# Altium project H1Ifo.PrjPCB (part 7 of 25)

## Sheet IfoIsc2B.SchDoc: D1800185
size C; Engineer: Daniel Sigg; DocumentNumber: 6; Revision: 4; SheetNumber: 6; SheetTotal: 11
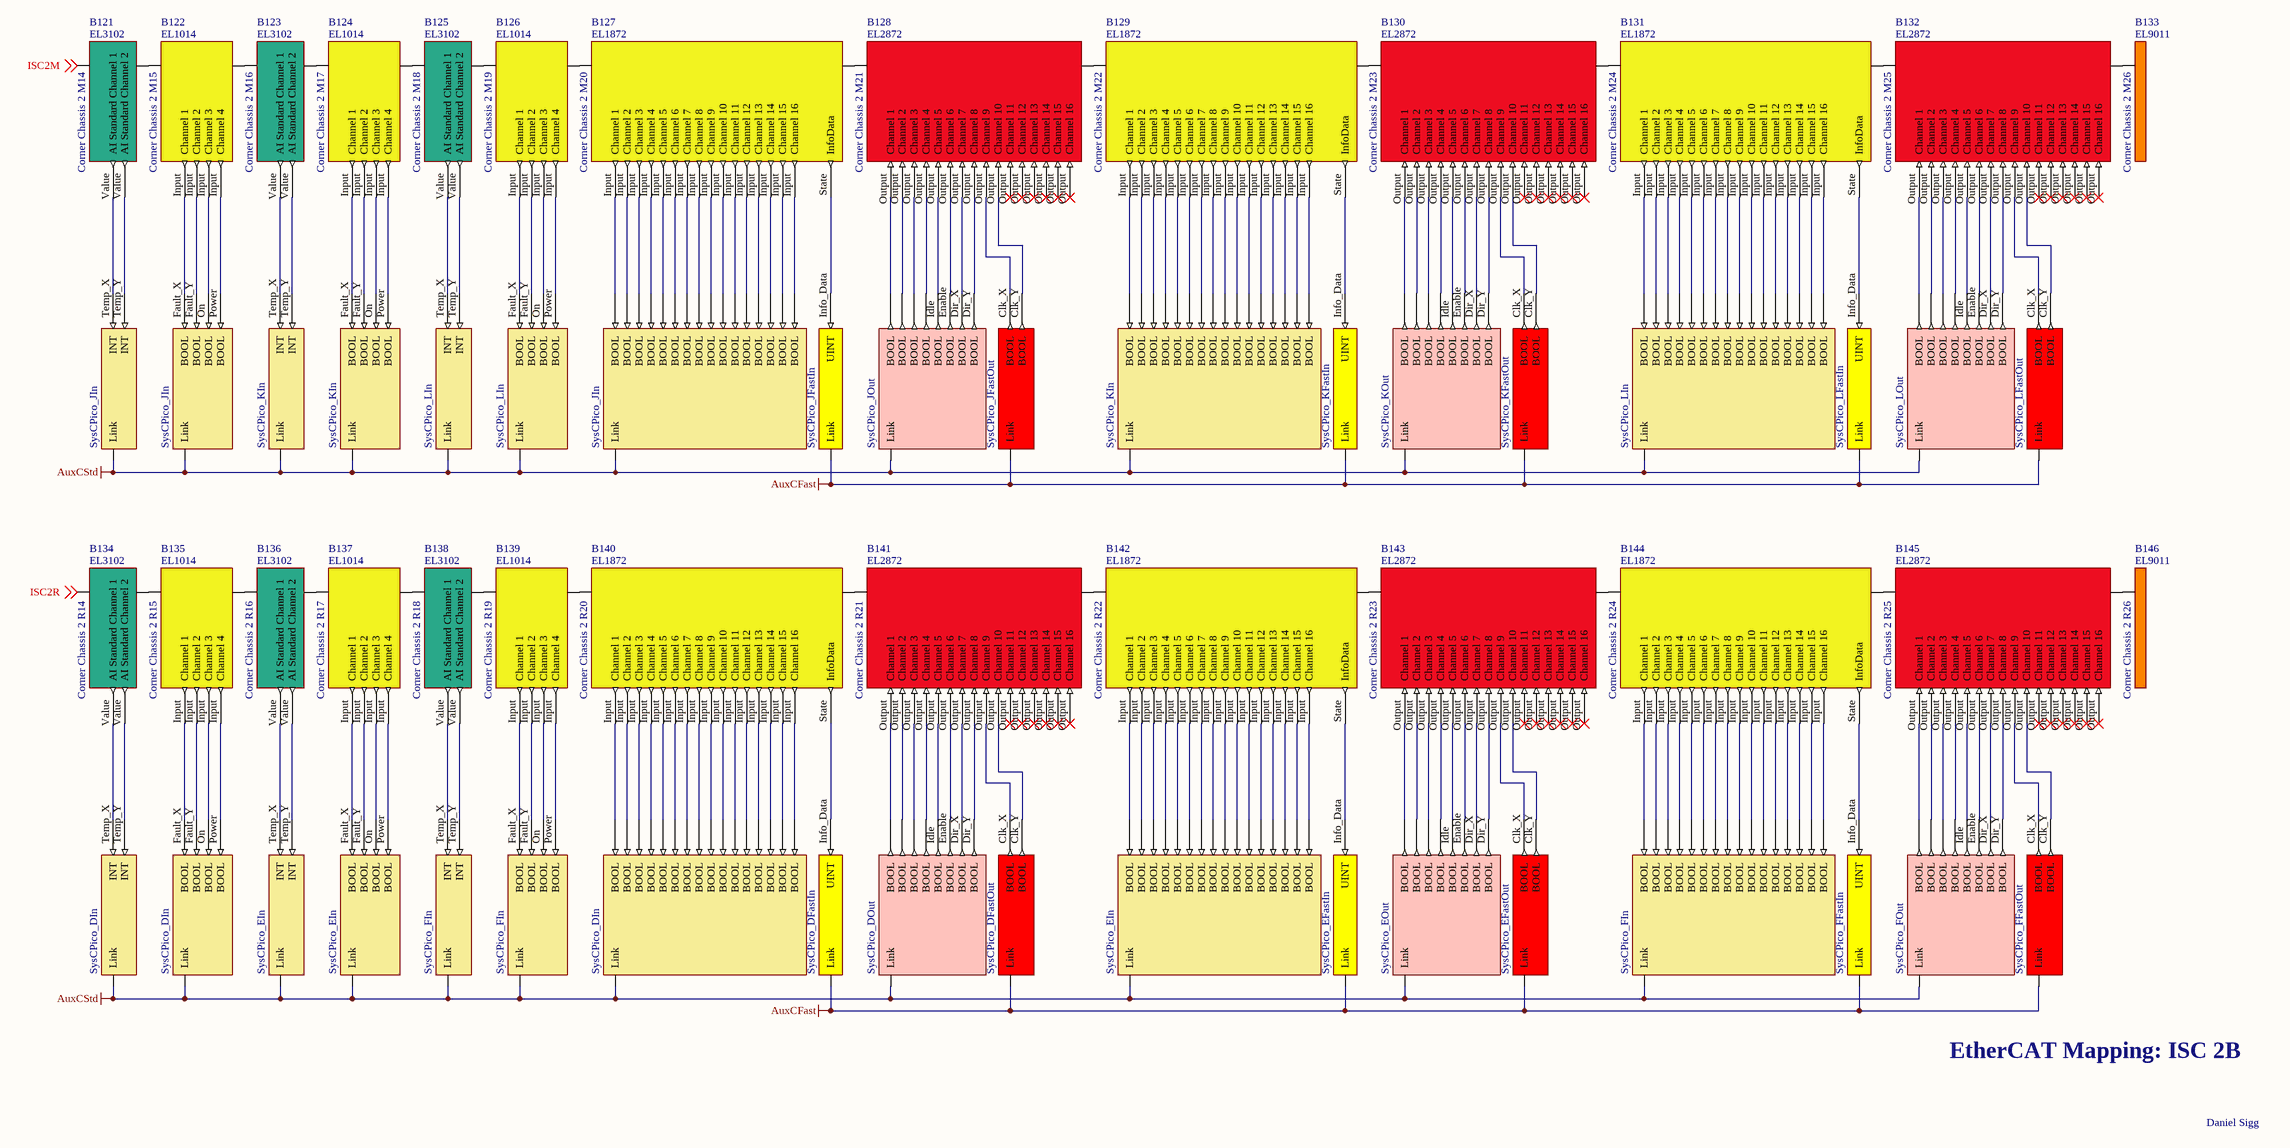
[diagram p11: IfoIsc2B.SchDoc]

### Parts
B121  Corner Chassis 2 M14  Part Number: EL3102  (mechanical)
B122  Corner Chassis 2 M15  Part Number: EL1014  (mechanical)
B123  Corner Chassis 2 M16  Part Number: EL3102  (mechanical)
B124  Corner Chassis 2 M17  Part Number: EL1014  (mechanical)
B125  Corner Chassis 2 M18  Part Number: EL3102  (mechanical)
B126  Corner Chassis 2 M19  Part Number: EL1014  (mechanical)
B127  Corner Chassis 2 M20  Part Number: EL1872  (mechanical)
B128  Corner Chassis 2 M21  Part Number: EL2872  (mechanical)
B129  Corner Chassis 2 M22  Part Number: EL1872  (mechanical)
B130  Corner Chassis 2 M23  Part Number: EL2872  (mechanical)
B131  Corner Chassis 2 M24  Part Number: EL1872  (mechanical)
B132  Corner Chassis 2 M25  Part Number: EL2872  (mechanical)
B133  Corner Chassis 2 M26  Part Number: EL9011  (mechanical)
B134  Corner Chassis 2 R14  Part Number: EL3102  (mechanical)
B135  Corner Chassis 2 R15  Part Number: EL1014  (mechanical)
B136  Corner Chassis 2 R16  Part Number: EL3102  (mechanical)
B137  Corner Chassis 2 R17  Part Number: EL1014  (mechanical)
B138  Corner Chassis 2 R18  Part Number: EL3102  (mechanical)
B139  Corner Chassis 2 R19  Part Number: EL1014  (mechanical)
B140  Corner Chassis 2 R20  Part Number: EL1872  (mechanical)
B141  Corner Chassis 2 R21  Part Number: EL2872  (mechanical)
B142  Corner Chassis 2 R22  Part Number: EL1872  (mechanical)
B143  Corner Chassis 2 R23  Part Number: EL2872  (mechanical)
B144  Corner Chassis 2 R24  Part Number: EL1872  (mechanical)
B145  Corner Chassis 2 R25  Part Number: EL2872  (mechanical)
B146  Corner Chassis 2 R26  Part Number: EL9011  (mechanical)
V74  SysCPico_DIn  (parts A,B,C of 3)  (no BOM)
V75  SysCPico_EIn  (parts A,B,C of 3)  (no BOM)
V76  SysCPico_FIn  (parts A,B,C of 3)  (no BOM)
V192  SysCPico_JFastIn  (no BOM)
V193  SysCPico_JOut  (no BOM)
V194  SysCPico_JFastOut  (no BOM)
V195  SysCPico_KFastIn  (no BOM)
V196  SysCPico_KOut  (no BOM)
V197  SysCPico_KFastOut  (no BOM)
V198  SysCPico_LFastIn  (no BOM)
V199  SysCPico_LOut  (no BOM)
V200  SysCPico_LFastOut  (no BOM)
V201  SysCPico_DFastIn  (no BOM)
V202  SysCPico_DOut  (no BOM)
V203  SysCPico_DFastOut  (no BOM)
V204  SysCPico_EFastIn  (no BOM)
V205  SysCPico_EOut  (no BOM)
V206  SysCPico_EFastOut  (no BOM)
V207  SysCPico_FFastIn  (no BOM)
V208  SysCPico_FOut  (no BOM)
V209  SysCPico_FFastOut  (no BOM)
V696  SysCPico_JIn  (parts A,B,C of 3)  (no BOM)
V697  SysCPico_KIn  (parts A,B,C of 3)  (no BOM)
V698  SysCPico_LIn  (parts A,B,C of 3)  (no BOM)

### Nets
AuxCFast: V192.0(Link) V194.0(Link) V195.0(Link) V197.0(Link) V198.0(Link) V200.0(Link) V201.0(Link) V203.0(Link) V204.0(Link) V206.0(Link) V207.0(Link) V209.0(Link)
AuxCStd: V74.0(Link) V74.1(Link) V74.2(Link) V75.0(Link) V75.1(Link) V75.2(Link) V76.0(Link) V76.1(Link) V76.2(Link) V193.0(Link) V196.0(Link) V199.0(Link) V202.0(Link) V205.0(Link) V208.0(Link) V696.0(Link) V696.1(Link) V696.2(Link) V697.0(Link) V697.1(Link) V697.2(Link) V698.0(Link) V698.1(Link) V698.2(Link)
ISC2M: B121.Ebus(A) ; off-sheet ISC2M
ISC2R: B134.Ebus(A) ; off-sheet ISC2R
NetB121_Ebus: B121.Ebus(B) B122.Ebus(A)
NetB121_Value: B121.Value(AI_Standard_Channel_1) V696.Temp_X(INT)
NetB121_Value: B121.Value(AI_Standard_Channel_2) V696.Temp_Y(INT)  [a separate net that carries the same name]
NetB122_Ebus: B122.Ebus(B) B123.Ebus(A)
NetB122_Input: B122.Input(Channel_1) V696.Fault_X(BOOL)
NetB122_Input: B122.Input(Channel_2) V696.Fault_Y(BOOL)  [a separate net that carries the same name]
NetB122_Input: B122.Input(Channel_3) V696.On(BOOL)  [a separate net that carries the same name]
NetB122_Input: B122.Input(Channel_4) V696.Power(BOOL)  [a separate net that carries the same name]
NetB123_Ebus: B123.Ebus(B) B124.Ebus(A)
NetB123_Value: B123.Value(AI_Standard_Channel_1) V697.Temp_X(INT)
NetB123_Value: B123.Value(AI_Standard_Channel_2) V697.Temp_Y(INT)  [a separate net that carries the same name]
NetB124_Ebus: B124.Ebus(B) B125.Ebus(A)
NetB124_Input: B124.Input(Channel_1) V697.Fault_X(BOOL)
NetB124_Input: B124.Input(Channel_2) V697.Fault_Y(BOOL)  [a separate net that carries the same name]
NetB124_Input: B124.Input(Channel_3) V697.On(BOOL)  [a separate net that carries the same name]
NetB124_Input: B124.Input(Channel_4) V697.Power(BOOL)  [a separate net that carries the same name]
NetB125_Ebus: B125.Ebus(B) B126.Ebus(A)
NetB125_Value: B125.Value(AI_Standard_Channel_1) V698.Temp_X(INT)
NetB125_Value: B125.Value(AI_Standard_Channel_2) V698.Temp_Y(INT)  [a separate net that carries the same name]
NetB126_Ebus: B126.Ebus(B) B127.Ebus(A)
NetB126_Input: B126.Input(Channel_1) V698.Fault_X(BOOL)
NetB126_Input: B126.Input(Channel_2) V698.Fault_Y(BOOL)  [a separate net that carries the same name]
NetB126_Input: B126.Input(Channel_3) V698.On(BOOL)  [a separate net that carries the same name]
NetB126_Input: B126.Input(Channel_4) V698.Power(BOOL)  [a separate net that carries the same name]
NetB127_Ebus: B127.Ebus(B) B128.Ebus(A)
NetB127_Input: B127.Input(Channel_1) V696.MotorX1(BOOL)
NetB127_Input: B127.Input(Channel_2) V696.MotorX2(BOOL)  [a separate net that carries the same name]
NetB127_Input: B127.Input(Channel_3) V696.MotorX3(BOOL)  [a separate net that carries the same name]
NetB127_Input: B127.Input(Channel_4) V696.MotorX4(BOOL)  [a separate net that carries the same name]
NetB127_Input: B127.Input(Channel_5) V696.MotorX5(BOOL)  [a separate net that carries the same name]
NetB127_Input: B127.Input(Channel_6) V696.MotorX6(BOOL)  [a separate net that carries the same name]
NetB127_Input: B127.Input(Channel_7) V696.MotorX7(BOOL)  [a separate net that carries the same name]
NetB127_Input: B127.Input(Channel_8) V696.MotorX8(BOOL)  [a separate net that carries the same name]
NetB127_Input: B127.Input(Channel_9) V696.MotorY1(BOOL)  [a separate net that carries the same name]
NetB127_Input: B127.Input(Channel_10) V696.MotorY2(BOOL)  [a separate net that carries the same name]
NetB127_Input: B127.Input(Channel_11) V696.MotorY3(BOOL)  [a separate net that carries the same name]
NetB127_Input: B127.Input(Channel_12) V696.MotorY4(BOOL)  [a separate net that carries the same name]
NetB127_Input: B127.Input(Channel_13) V696.MotorY5(BOOL)  [a separate net that carries the same name]
NetB127_Input: B127.Input(Channel_14) V696.MotorY6(BOOL)  [a separate net that carries the same name]
NetB127_Input: B127.Input(Channel_15) V696.MotorY7(BOOL)  [a separate net that carries the same name]
NetB127_Input: B127.Input(Channel_16) V696.MotorY8(BOOL)  [a separate net that carries the same name]
NetB127_State: B127.State(InfoData) V192.Info_Data(UINT)
NetB128_Ebus: B128.Ebus(B) B129.Ebus(A)
NetB128_Output: B128.Output(Channel_1) V193.MOTOR3(BOOL)
NetB128_Output: B128.Output(Channel_2) V193.MOTOR2(BOOL)  [a separate net that carries the same name]
NetB128_Output: B128.Output(Channel_3) V193.MOTOR1(BOOL)  [a separate net that carries the same name]
NetB128_Output: B128.Output(Channel_4) V193.MOTOR4(BOOL)  [a separate net that carries the same name]
NetB128_Output: B128.Output(Channel_5) V193.Idle(BOOL)  [a separate net that carries the same name]
NetB128_Output: B128.Output(Channel_6) V193.Enable(BOOL)  [a separate net that carries the same name]
NetB128_Output: B128.Output(Channel_7) V193.Dir_X(BOOL)  [a separate net that carries the same name]
NetB128_Output: B128.Output(Channel_8) V193.Dir_Y(BOOL)  [a separate net that carries the same name]
NetB128_Output: B128.Output(Channel_9) V194.Clk_X(BOOL)  [a separate net that carries the same name]
NetB128_Output: B128.Output(Channel_10) V194.Clk_Y(BOOL)  [a separate net that carries the same name]
NetB129_Ebus: B129.Ebus(B) B130.Ebus(A)
NetB129_Input: B129.Input(Channel_1) V697.MotorX1(BOOL)
NetB129_Input: B129.Input(Channel_2) V697.MotorX2(BOOL)  [a separate net that carries the same name]
NetB129_Input: B129.Input(Channel_3) V697.MotorX3(BOOL)  [a separate net that carries the same name]
NetB129_Input: B129.Input(Channel_4) V697.MotorX4(BOOL)  [a separate net that carries the same name]
NetB129_Input: B129.Input(Channel_5) V697.MotorX5(BOOL)  [a separate net that carries the same name]
NetB129_Input: B129.Input(Channel_6) V697.MotorX6(BOOL)  [a separate net that carries the same name]
NetB129_Input: B129.Input(Channel_7) V697.MotorX7(BOOL)  [a separate net that carries the same name]
NetB129_Input: B129.Input(Channel_8) V697.MotorX8(BOOL)  [a separate net that carries the same name]
NetB129_Input: B129.Input(Channel_9) V697.MotorY1(BOOL)  [a separate net that carries the same name]
NetB129_Input: B129.Input(Channel_10) V697.MotorY2(BOOL)  [a separate net that carries the same name]
NetB129_Input: B129.Input(Channel_11) V697.MotorY3(BOOL)  [a separate net that carries the same name]
NetB129_Input: B129.Input(Channel_12) V697.MotorY4(BOOL)  [a separate net that carries the same name]
NetB129_Input: B129.Input(Channel_13) V697.MotorY5(BOOL)  [a separate net that carries the same name]
NetB129_Input: B129.Input(Channel_14) V697.MotorY6(BOOL)  [a separate net that carries the same name]
NetB129_Input: B129.Input(Channel_15) V697.MotorY7(BOOL)  [a separate net that carries the same name]
NetB129_Input: B129.Input(Channel_16) V697.MotorY8(BOOL)  [a separate net that carries the same name]
NetB129_State: B129.State(InfoData) V195.Info_Data(UINT)
NetB130_Ebus: B130.Ebus(B) B131.Ebus(A)
NetB130_Output: B130.Output(Channel_1) V196.MOTOR3(BOOL)
NetB130_Output: B130.Output(Channel_2) V196.MOTOR2(BOOL)  [a separate net that carries the same name]
NetB130_Output: B130.Output(Channel_3) V196.MOTOR1(BOOL)  [a separate net that carries the same name]
NetB130_Output: B130.Output(Channel_4) V196.MOTOR4(BOOL)  [a separate net that carries the same name]
NetB130_Output: B130.Output(Channel_5) V196.Idle(BOOL)  [a separate net that carries the same name]
NetB130_Output: B130.Output(Channel_6) V196.Enable(BOOL)  [a separate net that carries the same name]
NetB130_Output: B130.Output(Channel_7) V196.Dir_X(BOOL)  [a separate net that carries the same name]
NetB130_Output: B130.Output(Channel_8) V196.Dir_Y(BOOL)  [a separate net that carries the same name]
NetB130_Output: B130.Output(Channel_9) V197.Clk_X(BOOL)  [a separate net that carries the same name]
NetB130_Output: B130.Output(Channel_10) V197.Clk_Y(BOOL)  [a separate net that carries the same name]
NetB131_Ebus: B131.Ebus(B) B132.Ebus(A)
NetB131_Input: B131.Input(Channel_1) V698.MotorX1(BOOL)
NetB131_Input: B131.Input(Channel_2) V698.MotorX2(BOOL)  [a separate net that carries the same name]
NetB131_Input: B131.Input(Channel_3) V698.MotorX3(BOOL)  [a separate net that carries the same name]
NetB131_Input: B131.Input(Channel_4) V698.MotorX4(BOOL)  [a separate net that carries the same name]
NetB131_Input: B131.Input(Channel_5) V698.MotorX5(BOOL)  [a separate net that carries the same name]
NetB131_Input: B131.Input(Channel_6) V698.MotorX6(BOOL)  [a separate net that carries the same name]
NetB131_Input: B131.Input(Channel_7) V698.MotorX7(BOOL)  [a separate net that carries the same name]
NetB131_Input: B131.Input(Channel_8) V698.MotorX8(BOOL)  [a separate net that carries the same name]
NetB131_Input: B131.Input(Channel_9) V698.MotorY1(BOOL)  [a separate net that carries the same name]
NetB131_Input: B131.Input(Channel_10) V698.MotorY2(BOOL)  [a separate net that carries the same name]
NetB131_Input: B131.Input(Channel_11) V698.MotorY3(BOOL)  [a separate net that carries the same name]
NetB131_Input: B131.Input(Channel_12) V698.MotorY4(BOOL)  [a separate net that carries the same name]
NetB131_Input: B131.Input(Channel_13) V698.MotorY5(BOOL)  [a separate net that carries the same name]
NetB131_Input: B131.Input(Channel_14) V698.MotorY6(BOOL)  [a separate net that carries the same name]
NetB131_Input: B131.Input(Channel_15) V698.MotorY7(BOOL)  [a separate net that carries the same name]
NetB131_Input: B131.Input(Channel_16) V698.MotorY8(BOOL)  [a separate net that carries the same name]
NetB131_State: B131.State(InfoData) V198.Info_Data(UINT)
NetB132_Ebus: B132.Ebus(B) B133.Ebus(A)
NetB132_Output: B132.Output(Channel_1) V199.MOTOR3(BOOL)
NetB132_Output: B132.Output(Channel_2) V199.MOTOR2(BOOL)  [a separate net that carries the same name]
NetB132_Output: B132.Output(Channel_3) V199.MOTOR1(BOOL)  [a separate net that carries the same name]
NetB132_Output: B132.Output(Channel_4) V199.MOTOR4(BOOL)  [a separate net that carries the same name]
NetB132_Output: B132.Output(Channel_5) V199.Idle(BOOL)  [a separate net that carries the same name]
NetB132_Output: B132.Output(Channel_6) V199.Enable(BOOL)  [a separate net that carries the same name]
NetB132_Output: B132.Output(Channel_7) V199.Dir_X(BOOL)  [a separate net that carries the same name]
NetB132_Output: B132.Output(Channel_8) V199.Dir_Y(BOOL)  [a separate net that carries the same name]
NetB132_Output: B132.Output(Channel_9) V200.Clk_X(BOOL)  [a separate net that carries the same name]
NetB132_Output: B132.Output(Channel_10) V200.Clk_Y(BOOL)  [a separate net that carries the same name]
NetB134_Ebus: B134.Ebus(B) B135.Ebus(A)
NetB134_Value: B134.Value(AI_Standard_Channel_1) V74.Temp_X(INT)
NetB134_Value: B134.Value(AI_Standard_Channel_2) V74.Temp_Y(INT)  [a separate net that carries the same name]
NetB135_Ebus: B135.Ebus(B) B136.Ebus(A)
NetB135_Input: B135.Input(Channel_1) V74.Fault_X(BOOL)
NetB135_Input: B135.Input(Channel_2) V74.Fault_Y(BOOL)  [a separate net that carries the same name]
NetB135_Input: B135.Input(Channel_3) V74.On(BOOL)  [a separate net that carries the same name]
NetB135_Input: B135.Input(Channel_4) V74.Power(BOOL)  [a separate net that carries the same name]
NetB136_Ebus: B136.Ebus(B) B137.Ebus(A)
NetB136_Value: B136.Value(AI_Standard_Channel_1) V75.Temp_X(INT)
NetB136_Value: B136.Value(AI_Standard_Channel_2) V75.Temp_Y(INT)  [a separate net that carries the same name]
NetB137_Ebus: B137.Ebus(B) B138.Ebus(A)
NetB137_Input: B137.Input(Channel_1) V75.Fault_X(BOOL)
NetB137_Input: B137.Input(Channel_2) V75.Fault_Y(BOOL)  [a separate net that carries the same name]
NetB137_Input: B137.Input(Channel_3) V75.On(BOOL)  [a separate net that carries the same name]
NetB137_Input: B137.Input(Channel_4) V75.Power(BOOL)  [a separate net that carries the same name]
NetB138_Ebus: B138.Ebus(B) B139.Ebus(A)
NetB138_Value: B138.Value(AI_Standard_Channel_1) V76.Temp_X(INT)
NetB138_Value: B138.Value(AI_Standard_Channel_2) V76.Temp_Y(INT)  [a separate net that carries the same name]
NetB139_Ebus: B139.Ebus(B) B140.Ebus(A)
NetB139_Input: B139.Input(Channel_1) V76.Fault_X(BOOL)
NetB139_Input: B139.Input(Channel_2) V76.Fault_Y(BOOL)  [a separate net that carries the same name]
NetB139_Input: B139.Input(Channel_3) V76.On(BOOL)  [a separate net that carries the same name]
NetB139_Input: B139.Input(Channel_4) V76.Power(BOOL)  [a separate net that carries the same name]
NetB140_Ebus: B140.Ebus(B) B141.Ebus(A)
NetB140_Input: B140.Input(Channel_1) V74.MotorX1(BOOL)
NetB140_Input: B140.Input(Channel_2) V74.MotorX2(BOOL)  [a separate net that carries the same name]
NetB140_Input: B140.Input(Channel_3) V74.MotorX3(BOOL)  [a separate net that carries the same name]
NetB140_Input: B140.Input(Channel_4) V74.MotorX4(BOOL)  [a separate net that carries the same name]
NetB140_Input: B140.Input(Channel_5) V74.MotorX5(BOOL)  [a separate net that carries the same name]
NetB140_Input: B140.Input(Channel_6) V74.MotorX6(BOOL)  [a separate net that carries the same name]
NetB140_Input: B140.Input(Channel_7) V74.MotorX7(BOOL)  [a separate net that carries the same name]
NetB140_Input: B140.Input(Channel_8) V74.MotorX8(BOOL)  [a separate net that carries the same name]
NetB140_Input: B140.Input(Channel_9) V74.MotorY1(BOOL)  [a separate net that carries the same name]
NetB140_Input: B140.Input(Channel_10) V74.MotorY2(BOOL)  [a separate net that carries the same name]
NetB140_Input: B140.Input(Channel_11) V74.MotorY3(BOOL)  [a separate net that carries the same name]
NetB140_Input: B140.Input(Channel_12) V74.MotorY4(BOOL)  [a separate net that carries the same name]
NetB140_Input: B140.Input(Channel_13) V74.MotorY5(BOOL)  [a separate net that carries the same name]
NetB140_Input: B140.Input(Channel_14) V74.MotorY6(BOOL)  [a separate net that carries the same name]
NetB140_Input: B140.Input(Channel_15) V74.MotorY7(BOOL)  [a separate net that carries the same name]
NetB140_Input: B140.Input(Channel_16) V74.MotorY8(BOOL)  [a separate net that carries the same name]
NetB140_State: B140.State(InfoData) V201.Info_Data(UINT)
NetB141_Ebus: B141.Ebus(B) B142.Ebus(A)
NetB141_Output: B141.Output(Channel_1) V202.MOTOR3(BOOL)
NetB141_Output: B141.Output(Channel_2) V202.MOTOR2(BOOL)  [a separate net that carries the same name]
NetB141_Output: B141.Output(Channel_3) V202.MOTOR1(BOOL)  [a separate net that carries the same name]
NetB141_Output: B141.Output(Channel_4) V202.MOTOR4(BOOL)  [a separate net that carries the same name]
NetB141_Output: B141.Output(Channel_5) V202.Idle(BOOL)  [a separate net that carries the same name]
NetB141_Output: B141.Output(Channel_6) V202.Enable(BOOL)  [a separate net that carries the same name]
NetB141_Output: B141.Output(Channel_7) V202.Dir_X(BOOL)  [a separate net that carries the same name]
NetB141_Output: B141.Output(Channel_8) V202.Dir_Y(BOOL)  [a separate net that carries the same name]
NetB141_Output: B141.Output(Channel_9) V203.Clk_X(BOOL)  [a separate net that carries the same name]
NetB141_Output: B141.Output(Channel_10) V203.Clk_Y(BOOL)  [a separate net that carries the same name]
NetB142_Ebus: B142.Ebus(B) B143.Ebus(A)
NetB142_Input: B142.Input(Channel_1) V75.MotorX1(BOOL)
NetB142_Input: B142.Input(Channel_2) V75.MotorX2(BOOL)  [a separate net that carries the same name]
NetB142_Input: B142.Input(Channel_3) V75.MotorX3(BOOL)  [a separate net that carries the same name]
NetB142_Input: B142.Input(Channel_4) V75.MotorX4(BOOL)  [a separate net that carries the same name]
NetB142_Input: B142.Input(Channel_5) V75.MotorX5(BOOL)  [a separate net that carries the same name]
NetB142_Input: B142.Input(Channel_6) V75.MotorX6(BOOL)  [a separate net that carries the same name]
NetB142_Input: B142.Input(Channel_7) V75.MotorX7(BOOL)  [a separate net that carries the same name]
NetB142_Input: B142.Input(Channel_8) V75.MotorX8(BOOL)  [a separate net that carries the same name]
NetB142_Input: B142.Input(Channel_9) V75.MotorY1(BOOL)  [a separate net that carries the same name]
NetB142_Input: B142.Input(Channel_10) V75.MotorY2(BOOL)  [a separate net that carries the same name]
NetB142_Input: B142.Input(Channel_11) V75.MotorY3(BOOL)  [a separate net that carries the same name]
NetB142_Input: B142.Input(Channel_12) V75.MotorY4(BOOL)  [a separate net that carries the same name]
NetB142_Input: B142.Input(Channel_13) V75.MotorY5(BOOL)  [a separate net that carries the same name]
NetB142_Input: B142.Input(Channel_14) V75.MotorY6(BOOL)  [a separate net that carries the same name]
NetB142_Input: B142.Input(Channel_15) V75.MotorY7(BOOL)  [a separate net that carries the same name]
NetB142_Input: B142.Input(Channel_16) V75.MotorY8(BOOL)  [a separate net that carries the same name]
NetB142_State: B142.State(InfoData) V204.Info_Data(UINT)
NetB143_Ebus: B143.Ebus(B) B144.Ebus(A)
NetB143_Output: B143.Output(Channel_1) V205.MOTOR3(BOOL)
NetB143_Output: B143.Output(Channel_2) V205.MOTOR2(BOOL)  [a separate net that carries the same name]
NetB143_Output: B143.Output(Channel_3) V205.MOTOR1(BOOL)  [a separate net that carries the same name]
NetB143_Output: B143.Output(Channel_4) V205.MOTOR4(BOOL)  [a separate net that carries the same name]
NetB143_Output: B143.Output(Channel_5) V205.Idle(BOOL)  [a separate net that carries the same name]
NetB143_Output: B143.Output(Channel_6) V205.Enable(BOOL)  [a separate net that carries the same name]
NetB143_Output: B143.Output(Channel_7) V205.Dir_X(BOOL)  [a separate net that carries the same name]
NetB143_Output: B143.Output(Channel_8) V205.Dir_Y(BOOL)  [a separate net that carries the same name]
NetB143_Output: B143.Output(Channel_9) V206.Clk_X(BOOL)  [a separate net that carries the same name]
NetB143_Output: B143.Output(Channel_10) V206.Clk_Y(BOOL)  [a separate net that carries the same name]
NetB144_Ebus: B144.Ebus(B) B145.Ebus(A)
NetB144_Input: B144.Input(Channel_1) V76.MotorX1(BOOL)
NetB144_Input: B144.Input(Channel_2) V76.MotorX2(BOOL)  [a separate net that carries the same name]
NetB144_Input: B144.Input(Channel_3) V76.MotorX3(BOOL)  [a separate net that carries the same name]
NetB144_Input: B144.Input(Channel_4) V76.MotorX4(BOOL)  [a separate net that carries the same name]
NetB144_Input: B144.Input(Channel_5) V76.MotorX5(BOOL)  [a separate net that carries the same name]
NetB144_Input: B144.Input(Channel_6) V76.MotorX6(BOOL)  [a separate net that carries the same name]
NetB144_Input: B144.Input(Channel_7) V76.MotorX7(BOOL)  [a separate net that carries the same name]
NetB144_Input: B144.Input(Channel_8) V76.MotorX8(BOOL)  [a separate net that carries the same name]
NetB144_Input: B144.Input(Channel_9) V76.MotorY1(BOOL)  [a separate net that carries the same name]
NetB144_Input: B144.Input(Channel_10) V76.MotorY2(BOOL)  [a separate net that carries the same name]
NetB144_Input: B144.Input(Channel_11) V76.MotorY3(BOOL)  [a separate net that carries the same name]
NetB144_Input: B144.Input(Channel_12) V76.MotorY4(BOOL)  [a separate net that carries the same name]
NetB144_Input: B144.Input(Channel_13) V76.MotorY5(BOOL)  [a separate net that carries the same name]
NetB144_Input: B144.Input(Channel_14) V76.MotorY6(BOOL)  [a separate net that carries the same name]
NetB144_Input: B144.Input(Channel_15) V76.MotorY7(BOOL)  [a separate net that carries the same name]
NetB144_Input: B144.Input(Channel_16) V76.MotorY8(BOOL)  [a separate net that carries the same name]
NetB144_State: B144.State(InfoData) V207.Info_Data(UINT)
NetB145_Ebus: B145.Ebus(B) B146.Ebus(A)
NetB145_Output: B145.Output(Channel_1) V208.MOTOR3(BOOL)
NetB145_Output: B145.Output(Channel_2) V208.MOTOR2(BOOL)  [a separate net that carries the same name]
NetB145_Output: B145.Output(Channel_3) V208.MOTOR1(BOOL)  [a separate net that carries the same name]
NetB145_Output: B145.Output(Channel_4) V208.MOTOR4(BOOL)  [a separate net that carries the same name]
NetB145_Output: B145.Output(Channel_5) V208.Idle(BOOL)  [a separate net that carries the same name]
NetB145_Output: B145.Output(Channel_6) V208.Enable(BOOL)  [a separate net that carries the same name]
NetB145_Output: B145.Output(Channel_7) V208.Dir_X(BOOL)  [a separate net that carries the same name]
NetB145_Output: B145.Output(Channel_8) V208.Dir_Y(BOOL)  [a separate net that carries the same name]
NetB145_Output: B145.Output(Channel_9) V209.Clk_X(BOOL)  [a separate net that carries the same name]
NetB145_Output: B145.Output(Channel_10) V209.Clk_Y(BOOL)  [a separate net that carries the same name]

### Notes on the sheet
- EtherCAT Mapping: ISC 2B
- Daniel Sigg

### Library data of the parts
B121 = TerminalEL3102: EtherCAT Terminal EL3102 2-chn Analog Input; Rail: Middle; BoxNextB: SIWFSHSY; BoxPrev: JSZGTQNB; PortPrevFull: 1072/B; PortPrevShort: B; Fullname: TIID^Vertex ISC (EtherCAT)^Corner Chassis 2 M0 (EK1100)^Corner Chassis 2 M14 (EL3102); BoxAddr: 1073; Disabled: False
B122 = TerminalEL1014: EtherCAT Terminal EL1014 4-channel digital input terminal 24 V DC; Rail: Middle; BoxNextB: TIRBAYNG; BoxPrev: RZQPCZGX; PortPrevFull: 1073/B; PortPrevShort: B; Fullname: TIID^Vertex ISC (EtherCAT)^Corner Chassis 2 M0 (EK1100)^Corner Chassis 2 M15 (EL1014); BoxAddr: 1074; Disabled: False
B123 = TerminalEL3102: EtherCAT Terminal EL3102 2-chn Analog Input; Rail: Middle; BoxNextB: IKTVSKEO; BoxPrev: SIWFSHSY; PortPrevFull: 1074/B; PortPrevShort: B; Fullname: TIID^Vertex ISC (EtherCAT)^Corner Chassis 2 M0 (EK1100)^Corner Chassis 2 M16 (EL3102); BoxAddr: 1075; Disabled: False
B124 = TerminalEL1014: EtherCAT Terminal EL1014 4-channel digital input terminal 24 V DC; Rail: Middle; BoxNextB: SBJYCGDM; BoxPrev: TIRBAYNG; PortPrevFull: 1075/B; PortPrevShort: B; Fullname: TIID^Vertex ISC (EtherCAT)^Corner Chassis 2 M0 (EK1100)^Corner Chassis 2 M17 (EL1014); BoxAddr: 1076; Disabled: False
B125 = TerminalEL3102: EtherCAT Terminal EL3102 2-chn Analog Input; Rail: Middle; BoxNextB: DIJNKDKY; BoxPrev: IKTVSKEO; PortPrevFull: 1076/B; PortPrevShort: B; Fullname: TIID^Vertex ISC (EtherCAT)^Corner Chassis 2 M0 (EK1100)^Corner Chassis 2 M18 (EL3102); BoxAddr: 1077; Disabled: False
B126 = TerminalEL1014: EtherCAT Terminal EL1014 4-channel digital input terminal 24 V DC; Rail: Middle; BoxNextB: KHLKEZMD; BoxPrev: SBJYCGDM; PortPrevFull: 1077/B; PortPrevShort: B; Fullname: TIID^Vertex ISC (EtherCAT)^Corner Chassis 2 M0 (EK1100)^Corner Chassis 2 M19 (EL1014); BoxAddr: 1078; Disabled: False
B127 = TerminalEL1872InfoData: EtherCAT Terminal EL1872 16-channel digital input terminal 24 V DC; Rail: Middle; BoxNextB: SXTWDOYQ; BoxPrev: DIJNKDKY; PortPrevFull: 1078/B; PortPrevShort: B; Fullname: TIID^Vertex ISC (EtherCAT)^Corner Chassis 2 M0 (EK1100)^Corner Chassis 2 M20 (EL1872); BoxAddr: 1079; Disabled: False
B128 = TerminalEL2872: EtherCAT Terminal EL2872 16-channel digital output terminal 24 V DC; Rail: Middle; BoxNextB: OTWWVOYN; BoxPrev: KHLKEZMD; PortPrevFull: 1079/B; PortPrevShort: B; Fullname: TIID^Vertex ISC (EtherCAT)^Corner Chassis 2 M0 (EK1100)^Corner Chassis 2 M21 (EL2872); BoxAddr: 1080; Disabled: False
B129 = TerminalEL1872InfoData: EtherCAT Terminal EL1872 16-channel digital input terminal 24 V DC; Rail: Middle; BoxNextB: GHLQMASE; BoxPrev: SXTWDOYQ; PortPrevFull: 1080/B; PortPrevShort: B; Fullname: TIID^Vertex ISC (EtherCAT)^Corner Chassis 2 M0 (EK1100)^Corner Chassis 2 M22 (EL1872); BoxAddr: 1081; Disabled: False
B130 = TerminalEL2872: EtherCAT Terminal EL2872 16-channel digital output terminal 24 V DC; Rail: Middle; BoxNextB: ZNXUPZJI; BoxPrev: OTWWVOYN; PortPrevFull: 1081/B; PortPrevShort: B; Fullname: TIID^Vertex ISC (EtherCAT)^Corner Chassis 2 M0 (EK1100)^Corner Chassis 2 M23 (EL2872); BoxAddr: 1082; Disabled: False
B131 = TerminalEL1872InfoData: EtherCAT Terminal EL1872 16-channel digital input terminal 24 V DC; Rail: Middle; BoxNextB: IVBKLTPI; BoxPrev: GHLQMASE; PortPrevFull: 1082/B; PortPrevShort: B; Fullname: TIID^Vertex ISC (EtherCAT)^Corner Chassis 2 M0 (EK1100)^Corner Chassis 2 M24 (EL1872); BoxAddr: 1083; Disabled: False
B132 = TerminalEL2872: EtherCAT Terminal EL2872 16-channel digital output terminal 24 V DC; Rail: Middle; BoxNextB: WZZCLEYN; BoxPrev: ZNXUPZJI; PortPrevFull: 1083/B; PortPrevShort: B; Fullname: TIID^Vertex ISC (EtherCAT)^Corner Chassis 2 M0 (EK1100)^Corner Chassis 2 M25 (EL2872); BoxAddr: 1084; Disabled: False
B133 = TerminalEL9011: EtherCAT Terminal EL9011 End; BoxType: TerminalPassive; Rail: Middle; BoxPrev: IVBKLTPI; PortPrevShort: B; Fullname: TIID^Vertex ISC (EtherCAT)^Corner Chassis 2 M0 (EK1100)^Corner Chassis 2 M26 (EL9011); Disabled: False
B134 = TerminalEL3102: EtherCAT Terminal EL3102 2-chn Analog Input; Rail: Right; BoxNextB: AKGJHUOM; BoxPrev: HMDXXCBQ; PortPrevFull: 1097/B; PortPrevShort: B; Fullname: TIID^Vertex ISC (EtherCAT)^Corner Chassis 2 R0 (EK1100)^Corner Chassis 2 R14 (EL3102); BoxAddr: 1098; Disabled: False
B135 = TerminalEL1014: EtherCAT Terminal EL1014 4-channel digital input terminal 24 V DC; Rail: Right; BoxNextB: LBDRVYAW; BoxPrev: IOJGNFIR; PortPrevFull: 1098/B; PortPrevShort: B; Fullname: TIID^Vertex ISC (EtherCAT)^Corner Chassis 2 R0 (EK1100)^Corner Chassis 2 R15 (EL1014); BoxAddr: 1099; Disabled: False
B136 = TerminalEL3102: EtherCAT Terminal EL3102 2-chn Analog Input; Rail: Right; BoxNextB: BNNFUBBH; BoxPrev: AKGJHUOM; PortPrevFull: 1099/B; PortPrevShort: B; Fullname: TIID^Vertex ISC (EtherCAT)^Corner Chassis 2 R0 (EK1100)^Corner Chassis 2 R16 (EL3102); BoxAddr: 1100; Disabled: False
B137 = TerminalEL1014: EtherCAT Terminal EL1014 4-channel digital input terminal 24 V DC; Rail: Right; BoxNextB: QNQGHBNU; BoxPrev: LBDRVYAW; PortPrevFull: 1100/B; PortPrevShort: B; Fullname: TIID^Vertex ISC (EtherCAT)^Corner Chassis 2 R0 (EK1100)^Corner Chassis 2 R17 (EL1014); BoxAddr: 1101; Disabled: False
B138 = TerminalEL3102: EtherCAT Terminal EL3102 2-chn Analog Input; Rail: Right; BoxNextB: TMCWVBXB; BoxPrev: BNNFUBBH; PortPrevFull: 1101/B; PortPrevShort: B; Fullname: TIID^Vertex ISC (EtherCAT)^Corner Chassis 2 R0 (EK1100)^Corner Chassis 2 R18 (EL3102); BoxAddr: 1102; Disabled: False
B139 = TerminalEL1014: EtherCAT Terminal EL1014 4-channel digital input terminal 24 V DC; Rail: Right; BoxNextB: FLACORTV; BoxPrev: QNQGHBNU; PortPrevFull: 1102/B; PortPrevShort: B; Fullname: TIID^Vertex ISC (EtherCAT)^Corner Chassis 2 R0 (EK1100)^Corner Chassis 2 R19 (EL1014); BoxAddr: 1103; Disabled: False
B140 = TerminalEL1872InfoData: EtherCAT Terminal EL1872 16-channel digital input terminal 24 V DC; Rail: Right; BoxNextB: POLUASBP; BoxPrev: TMCWVBXB; PortPrevFull: 1103/B; PortPrevShort: B; Fullname: TIID^Vertex ISC (EtherCAT)^Corner Chassis 2 R0 (EK1100)^Corner Chassis 2 R20 (EL1872); BoxAddr: 1104; Disabled: False
B141 = TerminalEL2872: EtherCAT Terminal EL2872 16-channel digital output terminal 24 V DC; Rail: Right; BoxNextB: ERHVSVTN; BoxPrev: FLACORTV; PortPrevFull: 1104/B; PortPrevShort: B; Fullname: TIID^Vertex ISC (EtherCAT)^Corner Chassis 2 R0 (EK1100)^Corner Chassis 2 R21 (EL2872); BoxAddr: 1105; Disabled: False
B142 = TerminalEL1872InfoData: EtherCAT Terminal EL1872 16-channel digital input terminal 24 V DC; Rail: Right; BoxNextB: DMUIBRKR; BoxPrev: POLUASBP; PortPrevFull: 1105/B; PortPrevShort: B; Fullname: TIID^Vertex ISC (EtherCAT)^Corner Chassis 2 R0 (EK1100)^Corner Chassis 2 R22 (EL1872); BoxAddr: 1106; Disabled: False
B143 = TerminalEL2872: EtherCAT Terminal EL2872 16-channel digital output terminal 24 V DC; Rail: Right; BoxNextB: XRRIRORA; BoxPrev: ERHVSVTN; PortPrevFull: 1106/B; PortPrevShort: B; Fullname: TIID^Vertex ISC (EtherCAT)^Corner Chassis 2 R0 (EK1100)^Corner Chassis 2 R23 (EL2872); BoxAddr: 1107; Disabled: False
B144 = TerminalEL1872InfoData: EtherCAT Terminal EL1872 16-channel digital input terminal 24 V DC; Rail: Right; BoxNextB: NTUCBACQ; BoxPrev: DMUIBRKR; PortPrevFull: 1107/B; PortPrevShort: B; Fullname: TIID^Vertex ISC (EtherCAT)^Corner Chassis 2 R0 (EK1100)^Corner Chassis 2 R24 (EL1872); BoxAddr: 1108; Disabled: False
B145 = TerminalEL2872: EtherCAT Terminal EL2872 16-channel digital output terminal 24 V DC; Rail: Right; BoxNextB: TLBTALWW; BoxPrev: XRRIRORA; PortPrevFull: 1108/B; PortPrevShort: B; Fullname: TIID^Vertex ISC (EtherCAT)^Corner Chassis 2 R0 (EK1100)^Corner Chassis 2 R25 (EL2872); BoxAddr: 1109; Disabled: False
B146 = TerminalEL9011: EtherCAT Terminal EL9011 End; BoxType: TerminalPassive; Rail: Right; BoxPrev: NTUCBACQ; PortPrevShort: B; Fullname: TIID^Vertex ISC (EtherCAT)^Corner Chassis 2 R0 (EK1100)^Corner Chassis 2 R26 (EL9011); Disabled: False
V74-V76 V696-V698 = Picomotor_PicomotorInStruct: PicomotorInStruct; BoxType: Variable; Instance: H1AuxCorner Instance; PLC: H1AuxCorner; Task: AuxCStd
V192 V195 V198 V201 V204 V207 = Picomotor_PicomotorFastInStruct: PicomotorFastInStruct; BoxType: Variable; Instance: H1AuxCorner Instance; PLC: H1AuxCorner; Task: AuxCFast
V193 V196 V199 V202 V205 V208 = Picomotor_PicomotorOutStruct: PicomotorOutStruct; BoxType: Variable; Instance: H1AuxCorner Instance; PLC: H1AuxCorner; Task: AuxCStd
V194 V197 V200 V203 V206 V209 = Picomotor_PicomotorFastOutStruct: PicomotorFastOutStruct; BoxType: Variable; Instance: H1AuxCorner Instance; PLC: H1AuxCorner; Task: AuxCFast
